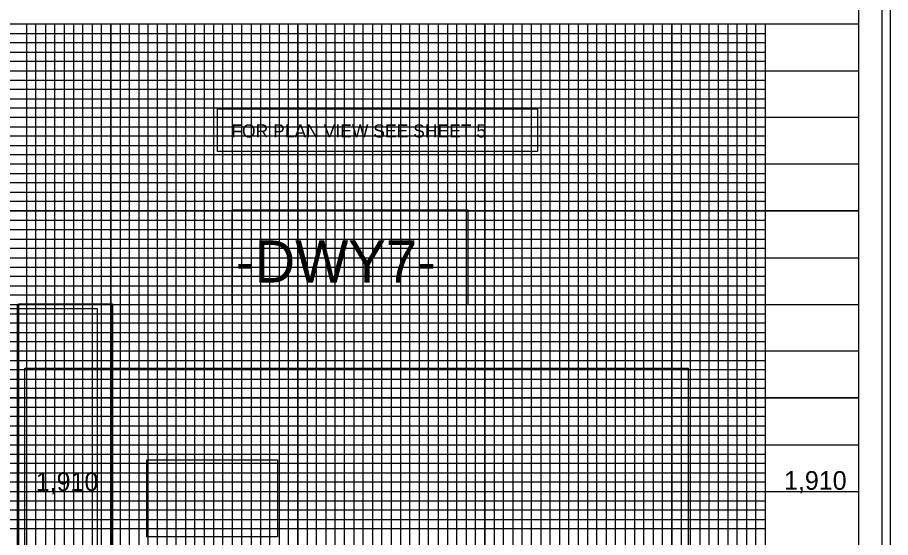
# Model space of a CAD drawing. Extents: x 557032 to 558930, y 525869 to 527437.
# Drawn here: x 558249.5 to 558716.5, y 526144.6 to 526422.7 of the extents above; entities that cross this region are included whole.
import ezdxf

# ---------------------------------------------------------------- set-up
doc = ezdxf.new("R2010")
doc.units = 0
for name, color, linetype in [('Exist Vertical Profile Vertical Axis Label', 7, 'Continuous'), ('Old_Level_63', 7, 'Continuous'), ('Prop Vertical Profile Curve Label', 7, 'Continuous'), ('Prop Vertical Profile Grade Label', 7, 'Continuous'), ('Prop VPI Label', 7, 'Continuous'), ('Raster_Level_4', 7, 'Continuous'), ('Sheet DOT Grid CELL', 7, 'Continuous'), ('Sheet Layout Profile Border Port 2', 7, 'Continuous'), ('Sheet Plot Border Inside CELL', 7, 'Continuous'), ('Sheet Plot Border Outside CELL', 7, 'Continuous'), ('Sheet Profile CELL', 7, 'Continuous'), ('Sheet Profile Grid Major CELL', 7, 'Continuous'), ('Sheet Profile Grid Middle CELL', 7, 'Continuous'), ('Sheet Profile Grid Minor CELL', 7, 'Continuous')]:
    doc.layers.add(name, color=color, linetype=linetype)

msp = doc.modelspace()

# ---------------------------------------------------------------- linework, layer by layer
at = {"layer": 'Old_Level_63'}
for points in [[(558249.63, 526269.34), (558299.63, 526269.34), (558299.63, 525919.34), (558249.63, 525919.34)], [(558250.34, 526269.61), (558300.34, 526269.61), (558300.34, 525919.61), (558250.34, 525919.61)]]:
    msp.add_lwpolyline(points, close=True, dxfattribs=at)
at = {"layer": 'Prop Vertical Profile Curve Label'}
for points in [[(558364.35, 526319.81), (558490.32, 526319.81), (558490.32, 526269.07), (558364.35, 526269.07)], [(558318.81, 526186.07), (558388.53, 526186.07), (558388.53, 526144.9), (558318.81, 526144.9)]]:
    msp.add_lwpolyline(points, close=True, dxfattribs=at)
at = {"layer": 'Prop VPI Label'}
for points in [[(558356.45, 526373.89), (558527.58, 526373.89), (558527.58, 526350.98), (558356.45, 526350.98)], [(558356.45, 526373.89), (558527.58, 526373.89), (558527.58, 526350.98), (558356.45, 526350.98)], [(558364.35, 526319.81), (558490.32, 526319.8), (558490.32, 526269.07), (558364.35, 526269.08)], [(558318.81, 526186.07), (558388.53, 526186.07), (558388.53, 526144.9), (558318.81, 526144.9)]]:
    msp.add_lwpolyline(points, close=True, dxfattribs=at)
at = {"layer": 'Raster_Level_4'}
for points in [[(557947.68, 526267.12), (558292.15, 526267.12), (558292.15, 525900.58), (557947.68, 525900.58)], [(558253.56, 526235.09), (558608.2, 526235.09), (558608.2, 525900.76), (558253.56, 525900.76)]]:
    msp.add_lwpolyline(points, close=True, dxfattribs=at)
at = {"layer": 'Sheet DOT Grid CELL'}
for p, q in [((557199.45, 526419.22), (558699.34, 526419.22)), ((558299.45, 526419.22), (558299.45, 525919.22)), ((558349.45, 526419.22), (558349.45, 525919.22)), ((558399.45, 526419.22), (558399.45, 525919.22)), ((558449.45, 526419.22), (558449.45, 525919.22)), ((558499.45, 526419.22), (558499.45, 525919.22)), ((558549.45, 526419.22), (558549.45, 525919.22)), ((558599.45, 526419.22), (558599.45, 525919.22)), ((558649.45, 526419.22), (558649.45, 525919.22)), ((557199.45, 526319.22), (558699.34, 526319.22)), ((557199.45, 526269.22), (558699.34, 526269.22)), ((557199.45, 526219.22), (558699.34, 526219.22)), ((557199.45, 526169.22), (558699.34, 526169.22))]:
    msp.add_line(p, q, dxfattribs=at)
at = {"layer": 'Sheet Layout Profile Border Port 2'}
msp.add_lwpolyline([(557249.45, 526419.22), (558649.45, 526419.22), (558649.45, 525919.22), (557249.45, 525919.22)], close=True, dxfattribs=at)
at = {"layer": 'Sheet Plot Border Inside CELL'}
msp.add_lwpolyline([(557045.45, 525891.67), (558711.95, 525891.67), (558711.95, 526946.77), (557045.45, 526946.77)], close=True, dxfattribs=at)
at = {"layer": 'Sheet Plot Border Outside CELL'}
msp.add_lwpolyline([(557032.45, 525869.22), (558716.45, 525869.22), (558716.45, 526969.22), (557032.45, 526969.22)], close=True, dxfattribs=at)
at = {"layer": 'Sheet Profile CELL'}
msp.add_line((557199.45, 526419.22), (558699.45, 526419.22), dxfattribs=at)
msp.add_lwpolyline([(558699.45, 526944.22), (557199.45, 526944.22), (557199.45, 525894.22), (558699.45, 525894.22)], close=True, dxfattribs=at)
at = {"layer": 'Sheet Profile Grid Major CELL'}
for p, q in [((558299.45, 526419.22), (558349.45, 526419.22)), ((558399.45, 526419.22), (558449.45, 526419.22)), ((558499.45, 526419.22), (558549.45, 526419.22)), ((558599.45, 526419.22), (558649.45, 526419.22)), ((558249.63, 526169.22), (558299.63, 526169.22))]:
    msp.add_line(p, q, dxfattribs=at)
for points in [[(558249.45, 525919.22), (558299.45, 525919.22), (558299.45, 526419.22), (558349.45, 526419.22), (558349.45, 525919.22), (558399.45, 525919.22), (558399.45, 526419.22), (558449.45, 526419.22), (558449.45, 525919.22), (558499.45, 525919.22), (558499.45, 526419.22), (558549.45, 526419.22), (558549.45, 526041.24)], [(558599.45, 526041.24), (558599.45, 526419.22), (558649.45, 526419.22), (558649.45, 525919.22)], [(558699.45, 526369.22), (557199.45, 526369.22)], [(558699.45, 526319.22), (557199.45, 526319.22), (557199.45, 526269.22), (558699.45, 526269.22)], [(558699.45, 526219.22), (557199.45, 526219.22), (557199.45, 526169.22), (558699.45, 526169.22)]]:
    msp.add_lwpolyline(points, dxfattribs=at)
at = {"layer": 'Sheet Profile Grid Middle CELL'}
for points in [[(558224.45, 526419.22), (558274.45, 526419.22), (558274.45, 525919.22), (558324.45, 525919.22), (558324.45, 526419.22), (558374.45, 526419.22), (558374.45, 525919.22), (558424.45, 525919.22), (558424.45, 526419.22), (558474.45, 526419.22), (558474.45, 525919.22), (558524.45, 525919.22), (558524.45, 526419.22), (558574.45, 526419.22), (558574.45, 526041.24)], [(558624.45, 526041.24), (558624.45, 526419.22)], [(557199.45, 526394.22), (558699.45, 526394.22)], [(558699.45, 526344.22), (557199.45, 526344.22), (557199.45, 526294.22), (558699.45, 526294.22)], [(558699.45, 526244.22), (557199.45, 526244.22), (557199.45, 526194.22), (558699.45, 526194.22)]]:
    msp.add_lwpolyline(points, dxfattribs=at)
at = {"layer": 'Sheet Profile Grid Minor CELL'}
for p, q in [((557249.45, 526414.22), (558649.45, 526414.22)), ((558649.45, 526409.22), (557249.45, 526409.22)), ((557249.45, 526404.22), (558649.45, 526404.22)), ((558649.45, 526399.22), (557249.45, 526399.22)), ((557249.45, 526389.22), (558649.45, 526389.22)), ((558649.45, 526384.22), (557249.45, 526384.22)), ((557249.45, 526379.22), (558649.45, 526379.22)), ((558649.45, 526374.22), (557249.45, 526374.22)), ((557249.45, 526364.22), (558649.45, 526364.22)), ((558649.45, 526359.22), (557249.45, 526359.22)), ((557249.45, 526354.22), (558649.45, 526354.22)), ((558649.45, 526349.22), (557249.45, 526349.22)), ((557249.45, 526339.22), (558649.45, 526339.22)), ((558649.45, 526334.22), (557249.45, 526334.22)), ((557249.45, 526329.22), (558649.45, 526329.22)), ((558649.45, 526324.22), (557249.45, 526324.22)), ((557249.45, 526314.22), (558649.45, 526314.22)), ((558649.45, 526309.22), (557249.45, 526309.22)), ((557249.45, 526304.22), (558649.45, 526304.22)), ((558649.45, 526299.22), (557249.45, 526299.22)), ((557249.45, 526289.22), (558649.45, 526289.22)), ((558649.45, 526284.22), (557249.45, 526284.22)), ((557249.45, 526279.22), (558649.45, 526279.22)), ((558649.45, 526274.22), (557249.45, 526274.22)), ((557249.45, 526264.22), (558649.45, 526264.22)), ((558649.45, 526259.22), (557249.45, 526259.22)), ((557249.45, 526254.22), (558649.45, 526254.22)), ((558649.45, 526249.22), (557249.45, 526249.22)), ((557249.45, 526239.22), (558649.45, 526239.22)), ((558649.45, 526234.22), (557249.45, 526234.22)), ((557249.45, 526229.22), (558649.45, 526229.22)), ((558649.45, 526224.22), (557249.45, 526224.37)), ((557249.45, 526214.22), (558649.45, 526214.22)), ((558649.45, 526209.22), (557249.45, 526209.22)), ((557249.45, 526204.22), (558649.45, 526204.22)), ((558649.45, 526199.22), (557249.45, 526199.22)), ((557249.45, 526189.22), (558649.45, 526189.22)), ((558649.45, 526184.22), (557249.45, 526184.22)), ((557249.45, 526179.22), (558649.45, 526179.22)), ((558649.45, 526174.22), (557249.45, 526174.22)), ((557249.45, 526164.22), (558649.45, 526164.22)), ((558649.45, 526159.22), (557249.45, 526159.22)), ((557249.45, 526154.22), (558649.45, 526154.22)), ((558649.45, 526149.22), (557249.45, 526149.22))]:
    msp.add_line(p, q, dxfattribs=at)
for points in [[(558244.45, 526419.22), (558254.45, 526419.22), (558254.45, 525919.22)], [(558259.45, 525919.22), (558259.45, 526419.22), (558264.45, 526419.22), (558264.45, 525919.22)], [(558269.45, 525919.22), (558269.45, 526419.22), (558279.45, 526419.22), (558279.45, 525919.22)], [(558284.45, 525919.22), (558284.45, 526419.22), (558289.45, 526419.22), (558289.45, 525919.22)], [(558294.45, 525919.22), (558294.45, 526419.22), (558304.45, 526419.22), (558304.45, 525919.22)], [(558309.45, 525919.22), (558309.45, 526419.22), (558314.45, 526419.22), (558314.45, 525919.22)], [(558319.45, 525919.22), (558319.45, 526419.22), (558329.45, 526419.22), (558329.45, 525919.22)], [(558334.45, 525919.22), (558334.45, 526419.22), (558339.45, 526419.22), (558339.45, 525919.22)], [(558344.45, 525919.22), (558344.45, 526419.22), (558354.45, 526419.22), (558354.45, 525919.22)], [(558359.45, 525919.22), (558359.45, 526419.22), (558364.45, 526419.22), (558364.45, 525919.22)], [(558369.45, 525919.22), (558369.45, 526419.22), (558379.45, 526419.22), (558379.45, 525919.22)], [(558384.45, 525919.22), (558384.45, 526419.22), (558389.45, 526419.22), (558389.45, 525919.22)], [(558394.45, 525919.22), (558394.45, 526419.22), (558404.45, 526419.22), (558404.45, 525919.22)], [(558409.45, 525919.22), (558409.45, 526419.22), (558414.45, 526419.22), (558414.45, 525919.22)], [(558419.45, 525919.22), (558419.45, 526419.22), (558429.45, 526419.22), (558429.45, 525919.22)], [(558434.45, 525919.22), (558434.45, 526419.22), (558439.45, 526419.22), (558439.45, 525919.22)], [(558444.45, 525919.22), (558444.45, 526419.22), (558454.45, 526419.22), (558454.45, 525919.22)], [(558459.45, 525919.22), (558459.45, 526419.22), (558464.45, 526419.22), (558464.45, 525919.22)], [(558469.45, 525919.22), (558469.45, 526419.22), (558479.45, 526419.22), (558479.45, 525919.22)], [(558484.45, 525919.22), (558484.45, 526419.22), (558489.45, 526419.22), (558489.45, 525919.22)], [(558494.45, 525919.22), (558494.45, 526419.22), (558504.45, 526419.22), (558504.45, 525919.22)], [(558509.45, 525919.22), (558509.45, 526419.22), (558514.45, 526419.22), (558514.45, 525919.22)], [(558519.45, 525919.22), (558519.45, 526419.22), (558529.45, 526419.22), (558529.45, 525919.22)], [(558534.45, 525919.22), (558534.45, 526419.22), (558539.45, 526419.22), (558539.45, 525919.22)], [(558544.45, 526041.24), (558544.45, 526419.22), (558554.45, 526419.22), (558554.45, 526041.24)], [(558559.45, 526041.24), (558559.45, 526419.22), (558564.45, 526419.22), (558564.45, 526041.24)], [(558569.45, 526041.24), (558569.45, 526419.22), (558579.45, 526419.22), (558579.45, 526041.24)], [(558584.45, 526041.24), (558584.45, 526419.22), (558589.45, 526419.22), (558589.45, 526041.24)], [(558594.45, 526041.24), (558594.45, 526419.22), (558604.45, 526419.22), (558604.45, 526041.24)], [(558609.45, 526041.24), (558609.45, 526419.22), (558614.45, 526419.22), (558614.45, 526041.24)], [(558619.45, 526041.24), (558619.45, 526419.22), (558629.45, 526419.22), (558629.45, 525919.22), (558634.45, 525919.22), (558634.45, 526419.22), (558639.45, 526419.22), (558639.45, 525919.22), (558644.45, 525919.22), (558644.45, 526419.22), (558649.45, 526419.22)]]:
    msp.add_lwpolyline(points, dxfattribs=at)

# ---------------------------------------------------------------- texts
at = {"layer": 'Exist Vertical Profile Vertical Axis Label'}
for p in [(558659.5, 526170.09), (558259.35, 526169.47)]:
    msp.add_text('1,910', height=10, dxfattribs=at).set_placement(p)
at = {"layer": 'Prop Vertical Profile Grade Label'}
msp.add_text('-DWY7-', height=22.5, dxfattribs=at).set_placement((558366.32, 526280.95))
at = {"layer": 'Prop VPI Label'}
msp.add_text('FOR PLAN VIEW SEE SHEET 5', height=7, dxfattribs=at).set_placement((558363.9, 526358.53))

doc.saveas('drawing.dxf')
